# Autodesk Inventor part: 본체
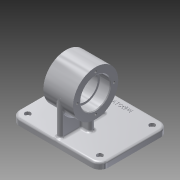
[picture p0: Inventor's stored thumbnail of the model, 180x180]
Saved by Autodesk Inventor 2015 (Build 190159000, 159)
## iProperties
Created: 2019-09
Part Number: 본체
Material: 알루미늄 6061
Document SubType Name: Modeling
Designer: now
Density: 2.7 g/cm^3
Appearance: 알루미늄 - 평지
Mass: 552.22 g
Surface Area: 493.79 cm^2
Volume: 204.526 cm^3
Author: now
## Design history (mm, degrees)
sketch "스케치1"
  geometry: L1 (-63, 49)-(63, 49); L2 (63, 49)-(63, -49); L3 (63, -49)-(-63, -49); L4 (-63, -49)-(-63, 49); 3 further points
  constraints: 8 end point, 2 midpoint, 2 parallel, 1 horizontal, 1 horizontal alignment, 1 perpendicular, 1 vertical alignment
  dimensions: "d0" = 126 distance of L2.end L3.end; "d1" = 98 distance of L3.end L1.start
extrude "돌출1" new body sketch "스케치1" distance "d2" = 9; taper "d3" = 0 deg
fillet "모깎기1" dims "d4" = 12
sketch "스케치2"
  geometry: A1 r 12 centre (-51, 37) between (-51, 49) and (-63, 37) reference; A2 r 12 centre (-51, -37) between (-63, -37) and (-51, -49) reference; A3 r 12 centre (51, -37) between (51, -49) and (63, -37) reference; A4 r 12 centre (51, 37) between (63, 37) and (51, 49) reference; 1 further point
hole "구멍1" sketch "스케치2" at (-51, -37), (51, -37), (51, 37), (-51, 37) diameter "d5" = 4.5; stored, may be unused: countersink angle "d9" = 90 deg, drill point angle "d11" = 118 deg; dims "d6" = 6, "d7" = 8, "d8" = 4.4, "d10" = 8
sketch "스케치15"
  geometry: C1 r 32 at (-13, 58.239); 2 further points
  constraints: 1 centre point
  dimensions: "d56" = 64 diameter of C1; "d70" = 36 horizontal distance of point (-49, 9) C1.centre
extrude "돌출8" join sketch "스케치15" stored distance "d57" = 42; taper "d58" = 0 deg
sketch "스케치18"
  geometry: L1 (63, -37)-(63, 37) reference; L2 (51, 49)-(-51, 49) reference; L3 (-4, 19)-(4, 19); L4 (4, 19)-(4, -45); L5 (4, -45)-(-4, -45); L6 (-4, -45)-(-4, 19); L7 (-4, 19)-(4, -45); L8 (4, 19)-(-4, -45); L9 (63, 37)-(63, -37) reference; L10 (51, -49)-(-51, -49) reference; L11 (-63, -37)-(-63, 37) reference; L12 (-51, 49)-(51, 49) reference; L13 (17, -9)-(-17, -9); L14 (-17, -9)-(-17, -17); L15 (-17, -17)-(17, -17); L16 (17, -17)-(17, -9); L17 (17, -9)-(-17, -17); L18 (-17, -9)-(17, -17); C1 r 4 at (51, 37) reference; C2 r 4 at (-51, -37) reference; C3 r 4 at (51, -37) reference; C4 r 4 at (-51, 37) reference; A1 r 12 centre (51, 37) between (63, 37) and (51, 49) reference; A2 r 12 centre (51, -37) between (51, -49) and (63, -37) reference; A3 r 12 centre (-51, -37) between (-63, -37) and (-51, -49) reference; A4 r 12 centre (-51, 37) between (-51, 49) and (-63, 37) reference; 5 further points
  constraints: 24 end point, 6 midpoint, 4 parallel, 2 horizontal, 2 perpendicular, 1 coincident
  dimensions: "d74" = 8 distance between parallel lines of L6 L4; "d75" = 36 distance from line of L10 point (0, -13); "d76" = 64 distance between parallel lines of L3 L5; "d77" = 8 distance between parallel lines of L15 L13; "d78" = 34 distance between parallel lines of L14 L16; "d79" = 63 distance from line of L1 point (0, -13); "d80" = 62 distance from line of point (0, -13) L2 (derived)
extrude "돌출11" join sketch "스케치18" distance "d81" = 50; taper "d82" = 0 deg
fillet "모깎기2" dims "d83" = 4
fillet "모깎기3" dims "d84" = 4
sketch "스케치19"
  geometry: C1 r 32 at (0, 0) reference; C2 r 21 at (0, 0); 1 further point
  constraints: 1 centre point, 1 coincident
  dimensions: "d85" = 42 diameter of C2
extrude "돌출12" cut sketch "스케치19" distance "d86" = 15; taper "d87" = 0 deg
sketch "스케치20"
  geometry: C1 r 21 at (0, 0) reference; C2 r 18 at (0, 0); 1 further point
  constraints: 1 centre point, 1 coincident
  dimensions: "d88" = 36 diameter of C2
extrude "돌출13" cut sketch "스케치20" distance "d89" = 12; taper "d90" = 0 deg
sketch "스케치21"
  geometry: C1 r 18 at (0, 0) reference; C2 r 21 at (0, 0); 1 further point
  constraints: 1 centre point, 1 coincident
  dimensions: "d91" = 42 diameter of C2
extrude "돌출14" cut sketch "스케치21" distance "d92" = 15; taper "d93" = 0 deg
sketch "스케치22"
  geometry: C1 r 21 at (0, 0) reference; 2 further points
  constraints: 1 horizontal alignment
  dimensions: "d94" = 26 distance of C1.centre point (26, 0)
hole "구멍2" sketch "스케치22" at (26, 0) diameter "d95" = 3.242; stored, may be unused: countersink angle "d99" = 90 deg, drill point angle "d101" = 118 deg; dims "d96" = 8, "d97" = 4, "d98" = 2, "d100" = 10
sketch "스케치23"
  geometry: C1 r 21 at (0, 0) reference; 2 further points
  constraints: 1 horizontal alignment
  dimensions: "d105" = 26 distance of C1.centre point (-26, 0)
hole "구멍3" sketch "스케치23" at (-26, 0) diameter "d106" = 3.242; stored, may be unused: countersink angle "d110" = 90 deg, drill point angle "d112" = 118 deg; dims "d107" = 8, "d108" = 4, "d109" = 2, "d111" = 10
sketch "스케치24"
  geometry: L1 (51, 49)-(-51, 49) reference; 3 further points
  constraints: 1 other
  dimensions: "d116" = 10 distance from line of point (0, 39) L1; "d117" = 63 horizontal distance of point (63, 37) point (0, 39)
feature "엠보싱1" sketch "스케치24" dims "d0" = 126, "d1" = 98, "d10" = 8, "d118" = 0.5, "d119" = 0
fillet "모깎기4" dims "d120" = 0.3, "d121" = 0.3
chamfer "모따기1" distance "d122" = 1; stored, may be unused: second distance "d123" = 2, angle "d124" = 45 deg
fillet "모깎기5" dims "d125" = 3
fillet "모깎기6" dims "d126" = 3
fillet "모깎기7" dims "d127" = 3
node "솔리드1"
pattern_circular "원형 패턴1" dims angle "d103" = 360 deg
pattern_circular "원형 패턴2" dims angle "d114" = 360 deg
node "절단 모서리 투영3"
